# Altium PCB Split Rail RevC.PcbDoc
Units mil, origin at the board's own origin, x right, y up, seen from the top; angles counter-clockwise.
Board outline 1325 x 805 mil, 2 copper layers (Top Layer, Bottom Layer); 37 components, 20 nets, 87 pads, 9 vias.
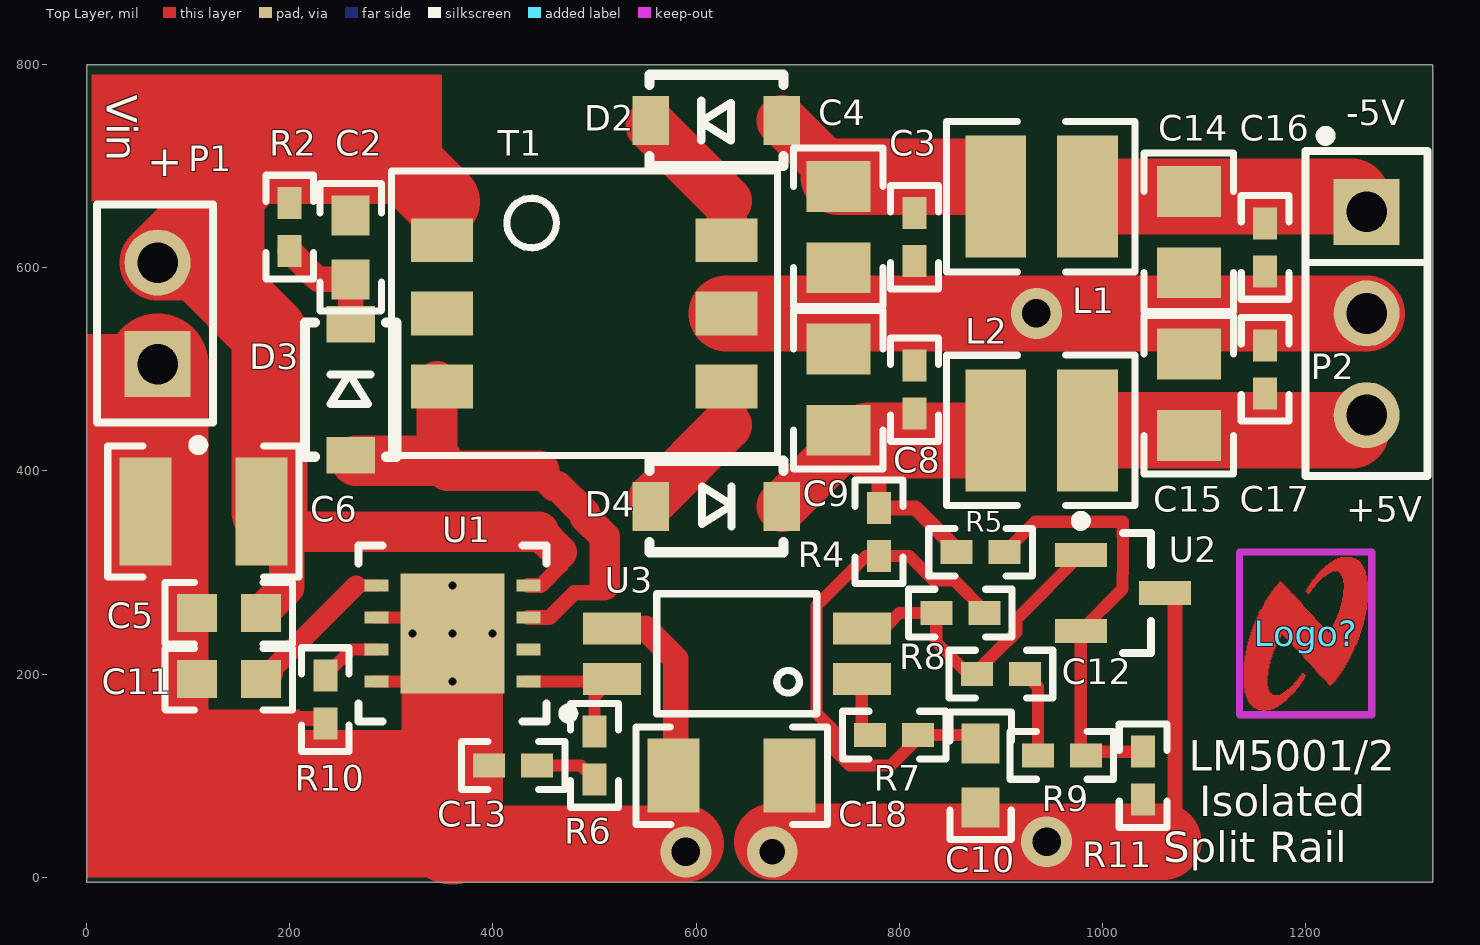
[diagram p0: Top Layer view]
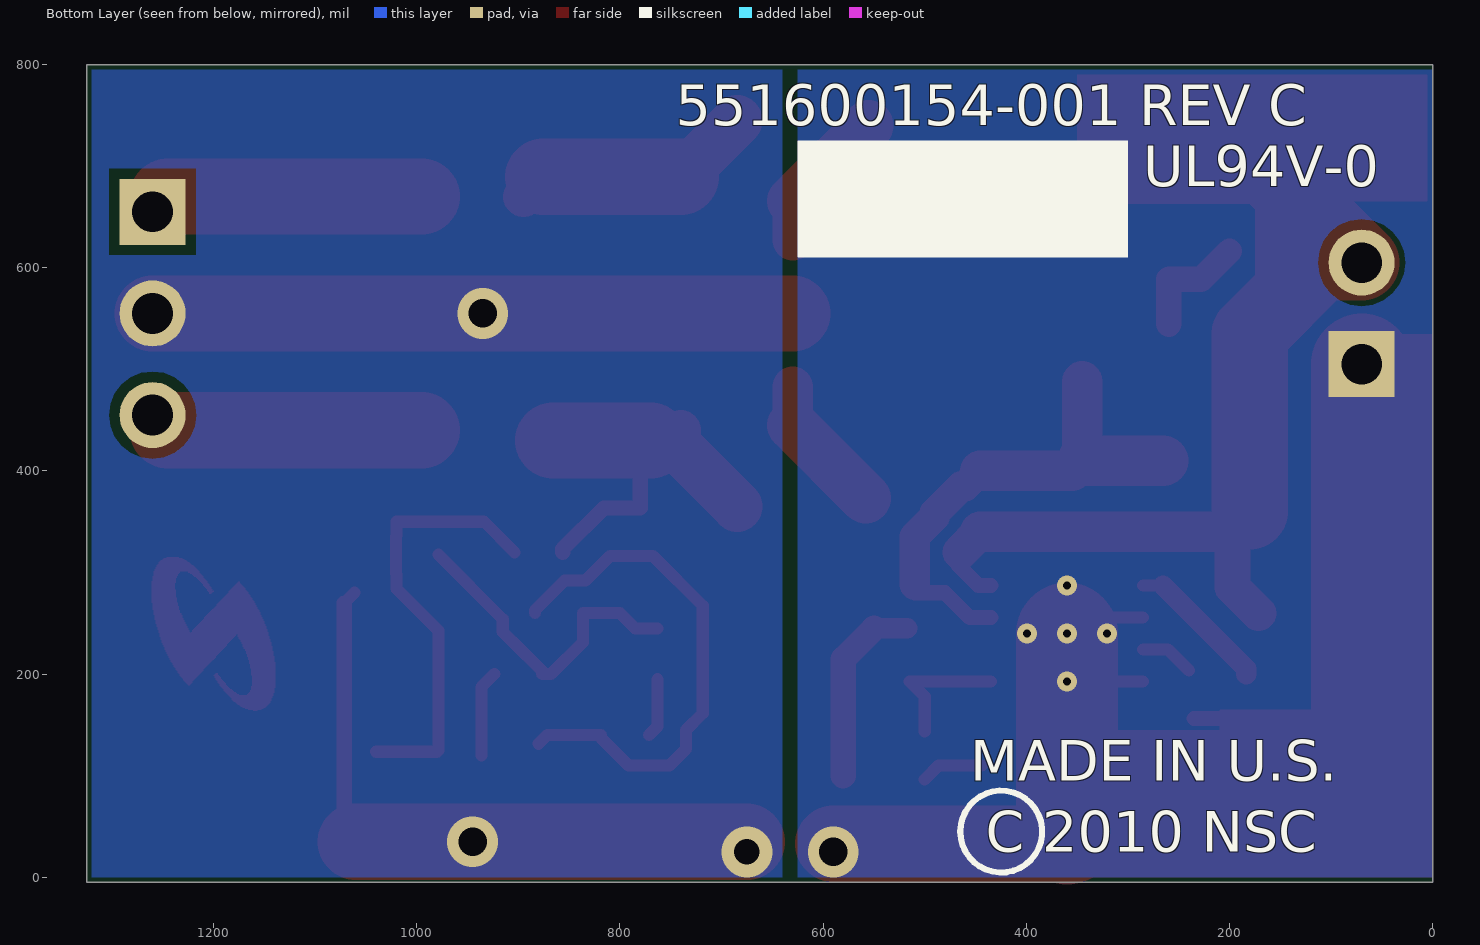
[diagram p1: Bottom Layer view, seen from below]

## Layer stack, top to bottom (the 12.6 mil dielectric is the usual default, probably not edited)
Top Layer: signal copper 1.4
Dielectric: core 12.6, FR-4, Dk 4.8
Bottom Layer: signal copper 1.4

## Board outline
0,-5 0,800 1325,800 1325,-5

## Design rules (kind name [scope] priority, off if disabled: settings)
Clearance "DC Power <25W" [All] p1: gap=10
Clearance [All] p2: gap=5
MinimumSolderMaskSliver [All] p1: minsoldermaskwidth=5
PlaneConnect [All] p1: planeconnectstyle=Direct reliefexpansion=20 reliefentries=4 reliefconductorwidth=10 reliefairgap=10
PolygonConnect [All] p1: connectstyle=Direct reliefconductorwidth=10 reliefentries=4 polygonreliefangle="90 Angle"
RoutingVias [All] p1: holewidth=13 width=25 viastyle="Through Hole" minholewidth=12 minwidth=25 maxholewidth=28 maxwidth=50
SMDNeckDown [All] p1: percent=750.000
SilkToSilkClearance [All] p1: silktosilkclearance=0
SilkscreenOverComponentPads [All] p1: minsilkscreentomaskgap=0
SolderMaskExpansion [All] p1: expansion=4
TestPointUsage [All] p1: valid=0 allowmultiple=FALSE
Testpoint [All] p1: side=15 testpointundercomponent=TRUE minsize=10 maxsize=100 preferedsize=60 minholesize=0 maxholesize=40 preferedholesize=32 testpointgrid=1 style=1023 order=0123456789
Width Ground_Out [InNet('NetC3_2')] p1: maxlimit=100 minlimit=10 preferedwidth=50
Width Ground_In [InNet('GND')] p2: maxlimit=100 minlimit=10 preferedwidth=35
Width [All] p3: maxlimit=200 minlimit=10 preferedwidth=20
20 further rules are at their usual default settings.

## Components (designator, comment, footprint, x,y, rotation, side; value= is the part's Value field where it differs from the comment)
C2 "GRM188R71H103KA01D" 0603 260,620 r270 top
C3 "C1005X5R1A104K" 0402 815,630 r270 top
C4 "EMK212BJ106KG-T" 0805_HV 740,640 r90 top
C5 "GRM188R71H104KA93D" 0603 140,260 r180 top
C6 "ECJ-4YF1H106Z" 1210 115,360 r180 top
C8 "C1005X5R1A104K" 0402 815,480 r270 top
C9 "EMK212BJ106KG-T" 0805_HV 740,480 r270 top
C10 "C1608Y5V1A105Z" 0603 880,100 r90 top
C11 "C1608Y5V1A105Z" 0603 140,195 r180 top
C12 "C1005X5R1A104K" 0402 900,200 r0 top
C13 "C1005X5R1A104K" 0402 420,110 r180 top
C14 "EMK212BJ106KG-T" 0805_HV 1085,635 r270 top
C15 "EMK212BJ106KG-T" 0805_HV 1085,475 r270 top
C16 "C1005X7R1C103K" 0402 1160,620 r270 top
C17 "C1005X7R1C103K" 0402 1160,500 r270 top
C18 "C3216C0G2J332J" 1206 635,100 r180 top
D2 "1N5819HW-7-F" SOD-123 620,745 r180 top
D3 "BAT41ZFILM" SOD-123 260,480 r90 top
D4 "1N5819HW-7-F" SOD-123 620,365 r0 top
L1 "ME3220-102MLB" ME3220 940,670 r0 top
L2 "ME3220-102MLB" ME3220 940,440 r0 top
Logo? "PCB Logo" Worldmark_CopperSolderMask_Small 1200,240 r0 top
P1 "TSW-102-07-G-S" TSW-102-07-X-S 70,555 r90 top
P2 "TSW-103-07-G-S" TSW-103-07-X-S 1260,555 r270 top
R2 "CRCW040210k0JNED" 0402 200,640 r270 top
R4 "CRCW040247R0JNED" 0402 780,340 r90 top
R5 "CRCW04022k21FKED" 0402 880,320 r0 top
R6 "CRCW0402249RFKED" 0402 500,120 r270 top
R7 "CRCW0402560RJNED" 0402 795,140 r180 top
R8 "CRCW040210k0JNED" 0402 860,260 r180 top
R9 "CRCW04024k99FKED" 0402 960,120 r180 top
R10 "CRCW040220k5FKED" 0402 235,175 r90 top
R11 "CRCW04022k21FKED" 0402 1040,100 r90 top
T1 "RL-8800" S32890 490,555 r0 top
U1 "LM5001SD" SDC08A 360,240 r180 top
U2 "LM431CCM3" MF03A_N 1020,280 r0 top
U3 "PS2811-1-M-A" PS2811-1 640,220 r180 top

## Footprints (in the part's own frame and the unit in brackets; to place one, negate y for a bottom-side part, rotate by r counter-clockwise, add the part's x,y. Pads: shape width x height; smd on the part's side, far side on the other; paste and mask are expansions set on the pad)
0402 [mm] "0402 from SM-752 data"
  rect 0.8x0.6 smd: 1(-0.6,0) 2(0.6,0)
  silkscreen extent -1.3,-0.6 1.3,0.6, body extent -0.55,-0.3 0.55,0.3, height 0.6
0603 [mm] "0603 from SM-752 data"
  rect 1x0.95 smd: 1(-0.8,0) 2(0.8,0)
  silkscreen extent -1.59,-0.77 1.59,0.77, body extent -0.87,-0.47 0.87,0.47, height 0.85
0805_HV [mil] "0805 with 30mil clearance between pads"
  rect 50x63 smd: 1(-40,0) 2(40,0)
  silkscreen extent -78,-44 78,44, body extent -43,-29 43,29, height 43
1206 [mm] "1206 from SM-752 data"
  rect 1.3x1.85 smd: 1(-1.45,0) 2(1.45,0)
  silkscreen extent -2.39,-1.22 2.39,1.22, body extent -1.7,-0.9 1.7,0.9, height 1.35
1210 [mm] "1210 from SM-752 data"
  rect 1.3x2.7 smd: 1(-1.45,0) 2(1.45,0)
  silkscreen extent -2.39,-1.64 2.39,1.64, body extent -1.7,-1.35 1.7,1.35, height 1.35
ME3220 [mm] "Coilcraft SMT Power Inductor ME3220 inductors"
  rect 1.52x3.05 smd: 1(-1.145,0) 2(1.145,0)
  silkscreen extent -2.38,-1.88 2.34,1.88, body extent -1.75,-1.41 1.75,1.4
MF03A_N [mm] "SOT23, 3-Leads, Body 2.9x1.3mm, Pitch 0.95mm, Lead Span 2.4mm, IPC Medium Density"
  rect 1.3x0.6 smd: 1(-1.05,0.95) 2(-1.05,-0.95) 3(1.05,0)
  silkscreen extent -1.17,-1.5 0.7,1.92, body extent -0.7,-1.5 0.7,1.5, height 1.12
PS2811-1 [mm] "NEC optocoupler"
  rect 1.45x0.8 smd: 1(-3.125,0.635) 2(-3.125,-0.635) 3(3.125,-0.635) 4(3.125,0.635)
  silkscreen extent -2,-1.5 2,1.5, body extent -2.2,-1.5 2.2,1.5, height 2.1
S32890 [mil] "Renco recommended land pattern"
  rect 61x43 smd: 1(-140,72) 2(-140,0) 3(-140,-72) 4(140,-72) 5(140,0) 6(140,72)
  silkscreen extent -190,-140 190,140, body extent -120,-137 120,138, height 225
SDC08A [mm] "SON, 8-Leads, Body 4x4mm, Pitch 0.8mm, NSC Recommended"
  rect 0.6x0.3 smd paste-0.15 mask+0.051: 1(-1.9,1.2) 2(-1.9,0.4) 3(-1.9,-0.4) 4(-1.9,-1.2) 5(1.9,-1.2) 6(1.9,-0.4) 7(1.9,0.4) 8(1.9,1.2)
  rect 2.6x3 smd paste-1.5 mask+0.051: 9(0,0)
  silkscreen extent -3.03,-2.2 2.35,2.2, body extent -2.05,-2.05 2.05,2.05, height 0.8
SOD-123 [mm] "On Semi recommended land pattern"
  rect 0.915x1.22 smd: 1(-1.637,0) 2(1.637,0)
  silkscreen extent -1.68,-1.14 1.68,1.14, body extent -1.42,-0.9 1.42,0.9, height 1.35
TSW-102-07-X-S [mm] "Samtec 100 mil 1x2 head, 230 mil above insulator"
  rect 1.65x1.65 hole 1.016 mask+0: 1(-1.27,0)
  round 1.65 hole 1.016 mask+0: 2(1.27,0)
  silkscreen extent -3.42,-1.38 2.72,1.51, body extent -2.54,-1.27 2.54,1.27, height 8.38
TSW-103-07-X-S [mm] "Samtec Header, 100mil, 1x3"
  rect 1.65x1.65 hole 1.016: 1(-2.54,0)
  round 1.65 hole 1.016: 2(0,0) 3(2.54,0)
  silkscreen extent -4.57,-1.52 4.06,1.52, body extent -3.81,-1.27 3.81,1.27, height 8.38
Worldmark_CopperSolderMask_Small [mil]
  Top Layer region: 926 vertices and 0 holes, not listed, extent -61,-76 61,75
  Top Layer keep-out lines w7: -65,-80 65,-80 65,80 -65,80 -65,-80

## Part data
C2: "Ceramic, X7R, 50V, 10%"
C3 C8 C12 C13: "Ceramic, X5R, 10V, 10%"
C4 C9 C14 C15: "Ceramic, X5R, 16V, 10%"
C5: library part GRM188R71E104KA01D, "Ceramic, X7R, 25V, 10%"
C6: library part C3225X7R1E106M, "Ceramic, X7R, 25V, 20%"
C10 C11: "Ceramic, Y5V, 10V, 80%"
C16 C17: "Ceramic, X7R, 16V, 10%"
C18: "Ceramic, C0G/NP0, 630V, 5%"
D2 D4: "Vr = 40V, Io = 1A, Vf = 0.45V"
D3: "Vr = 100V, Io = 0.2A, Vf = 1V"
L1 L2: "Drum Core, 2.6A, 0.058 Ohm"
Logo?: library part "NSC Logo", "National Semiconductor logo or worldmark"
P1: "Header, TH, 100mil, 1x2, Gold plated, 230 mil above insulator"
P2: "Header, TH, 100mil, 1x3, Gold plated, 230 mil above insulator"
R2 R4 R7 R8: "5%, 0.063W"
R5 R6 R9 R10 R11: "1%, 0.063W"
T1: "Transformer"
U1: library part LM5002SD, "High Voltage Switch Mode Regulator"
U2: "Adjustable Precision Zener Shunt Regulator"
U3: "Low Input Current, Hight CTR Photocoupler"

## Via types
v1: diameter 19.68, hole 7.87, Top Layer to Bottom Layer, tented top, 5 vias
v2: diameter 50, hole 28, Top Layer to Bottom Layer, 3 vias
v3: diameter 50, hole 25, Top Layer to Bottom Layer, 1 vias

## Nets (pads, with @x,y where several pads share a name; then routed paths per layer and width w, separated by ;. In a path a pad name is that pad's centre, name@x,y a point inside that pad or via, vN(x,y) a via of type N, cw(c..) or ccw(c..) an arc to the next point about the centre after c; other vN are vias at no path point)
GND: C5.2 C6.2 C11.2 C13.2 C18.2 P1.1 R10.1 U1.6 U1.8 U1.9 U3.3 | length 1518.9
  Top Layer w12: U1.8 312.76,192.76 v1(360,240) 344.25,255.75 U1.6
  Top Layer w15: 201.38,156.38 R10.1@235,156.38
  Top Layer w20: U3.3 550,245
  Top Layer w25: 550,245 580,215 C18.2@580,100
  Top Layer w75: 360,43.13 370,33.13 v2@590,33.13
  Top Layer w100: P1.1 70,130 150,50 350,50 ; 360,43.13 v1(360,240)
  other v1: 360,192.76 320.63,240 399.37,240 360,287.24
  other v2: 590,25
NetC2_1: C2.1 C5.1 C6.1 P1.2 R2.1 T1.1 U1.4 | length 1095.4
  Top Layer w15: U1.4 447.24,287.24 467.24,307.24 467.24,317.97 465.1,320.11
  Top Layer w30: C6.1@195,350 197.09,350.04 C6.1@197.3,350.05
  Top Layer w35: C5.1 197.09,285.59 197.09,350.04 C6.1@197.09,360 ; C6.1@197.3,350.05 207.35,340 ; 445.21,340 465.1,320.11
  Top Layer w40: 207.35,340 445.21,340
  Top Layer w75: C6.1@180,360 180,535 110,605 P1.2 165,700 315,700 350,665
NetC2_2: C2.2 D3.2 R2.2 | length 115.6
  Top Layer w25: R2.2 227.87,588.5 C2.2 D3.2
NetC3_1: C3.1 C4.2 D2.1 L1.1 | length 241.5
  Top Layer w40: L1.1@875.45,689.47 L1.1
  Top Layer w50: D2.1 C4.2@740,689.47
  Top Layer w75: C4.2@740,689.47 L1.1@875.45,689.47
NetC3_2: C3.2 C4.1 C8.1 C9.1 C10.1 C14.2 C15.1 C16.2 C17.1 C18.1 P2.2 R11.1 T1.5 U2.3 | length 1260.5
  Top Layer w12: U2.3 U2.3@1071.34,270
  Top Layer w15: 1071.34,38.66 U2.3@1071.34,270
  Top Layer w75: T1.5 P2.2 ; v3@675,35 1060,35
  other v2: 945,35 935,555
  other v3: 675,25
NetC8_2: C8.2 C9.2 D4.2 L2.1 R4.2 R5.1 | length 360.8
  Top Layer w15: C9.2@770,430 780,420 R4.2 815.85,363.62 856.38,323.09 R5.1
  Top Layer w40: C9.2@740,420.53 C9.2
  Top Layer w50: D4.2 C9.2@740,420.53
  Top Layer w75: C9.2@770,430 L2.1@865.98,430
NetC10_2: C10.2 R4.1 R7.1 R8.1 | length 527.9
  Top Layer w12: C10.2 871.5,140 R7.1 818.62,137.06 791.56,110 751.19,110 735,126.19 735,145 718.49,161.51 718.49,267.38 767.49,316.38 800,316.38 809.81,316.38 834,292.19 854.38,292.19 883.62,262.94 R8.1
NetC11_1: C11.1 U1.5 | length 140.9
  Top Layer w12: 265.47,287.24 U1.5
  Top Layer w20: C11.1@183.45,200 183.45,205.22 265.47,287.24
NetC12_1: C12.1 R8.2 U2.1 U3.2 | length 321.2
  Top Layer w12: U3.2 785,245 800,260 R8.2 836.38,231.38 867.76,200 C12.1 876.38,202.94 905.62,232.19 906,232.19 915.37,241.56 915.37,254.11 U2.1
NetC12_2: C12.2 R9.2 | length 85.3
  Top Layer w12: C12.2 936.38,187.24 R9.2
NetC13_1: C13.1 R6.2 | length 67.1
  Top Layer w12: C13.1 486.38,110 R6.2 R6.2@496.38,100
NetC14_1: C14.1 C16.1 L1.2 P2.1 | length 271.2
  Top Layer w50: P2.1@1245,670 P2.1
  Top Layer w75: L1.2@995,670 P2.1@1245,670
NetC15_2: C15.2 C17.2 L2.2 P2.3 | length 271.2
  Top Layer w50: P2.3@1245,440 P2.3
  Top Layer w75: L2.2@995,440 P2.3@1245,440
NetD2_2: D2.2 T1.6 | length 143.8
  Top Layer w40: T1.6 630,665.53
  Top Layer w50: D2.2@555.53,740 630,665.53
NetD3_1: D3.1 T1.3 U1.3 | length 473.8
  Top Layer w15: U1.3 455.75,255.75 480,280 510,280
  Top Layer w30: 445.32,400 460.32,385 463.85,385 490.21,358.64 490.21,355.1 510,335.32 510,288.12
  Top Layer w40: 345,410 T1.3@345,488 ; 355,400 445.32,400
  Top Layer w50: D3.1@265.53,410 345,410
NetD4_1: D4.1 T1.4 | length 139.8
  Top Layer w40: 630,445 T1.4
  Top Layer w50: D4.1@558.03,373.03 630,445
NetR5_2: R5.2 R9.1 R11.2 U2.2 | length 433.1
  Top Layer w12: R5.2 933.62,350 1020,350 1020,336.09 1020.25,335.84 1020.25,298.94 1019.75,298.44 1019.75,283.69 U2.2 978.66,124.96 980,123.62 R11.2
NetR6_1: R6.1 U1.1 U3.4 | length 135.2
  Top Layer w12: U1.1 514.72,192.76 500,178.03 R6.1
NetR7_2: R7.2 U3.1 | length 58.5
  Top Layer w12: U3.1 763.03,148.35 R7.2
NetR10_2: R10.2 U1.7 | length 53.7
  Top Layer w12: R10.2@240,203.62 260.63,224.25 U1.7
pads on no net: T1.2 U1.2

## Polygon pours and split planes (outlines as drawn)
GND on Bottom Layer "VinGroundPlane" (solid, pour order 1000): 0,0 625,0 625,795 0,795 0,0
NetC3_2 on Bottom Layer "OutGround" (solid, pour order 1001): 640,0 1320,0 1320,795 640,795

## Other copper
Top Layer:
  rectangle net NetC2_1: 5,665 350,790
  rectangle net NetC2_1: 136.95,585 175,671.95
  rectangle net GND: 20,0 210,165
  rectangle net GND: 0,0 35,535
  rectangle net GND: 200,85 330,145

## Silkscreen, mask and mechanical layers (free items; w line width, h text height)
Top Overlay:
  text "Vin" at 20,770 h30 r270
  text "-5V" at 1240,740 h25
  text "+" at 60,690 h30
  text "+5V" at 1240,350 h25
  text "LM5001/2" at 1085,105 h30
  text "Isolated" at 1095,60 h30
  text "Split Rail" at 1060,15 h30
Bottom Overlay:
  circle w6: c424.69,45 r40.31
  rectangle: 300,610 625,725
  text "551600154-001 REV C" at 745,740 h40
  text "UL94V-0" at 285,680 h40
  text "MADE IN U.S." at 455,95 h40
  text "C 2010 NSC" at 440,25 h40
Mechanical 1:
  the board outline again, w10

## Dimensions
0,-5 to -10,795 on Mechanical 2
0,-5 to 1325,-30 on Mechanical 2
